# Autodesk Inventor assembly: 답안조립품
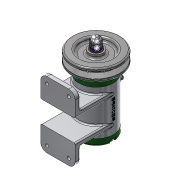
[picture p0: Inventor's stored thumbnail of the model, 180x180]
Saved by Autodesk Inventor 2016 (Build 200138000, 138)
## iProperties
Created: 2017-02
Part Number: 답안조립품
Material: 일반
Document SubType Name: Assembly
Designer: H
Author: H
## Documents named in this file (16)
- C:\Users\CAMTIC\Desktop\470207V1008\답안조립품.iam
- C:\Users\CAMTIC\Desktop\470207V1008\본체.ipt
- C:\Users\CAMTIC\Desktop\470207V1008\V벨트풀리.ipt
- C:\Users\CAMTIC\Desktop\470207V1008\너트 M 8.ipt
- C:\Users\CAMTIC\Desktop\470207V1008\니플 M 6 x 0.75.ipt
- C:\Users\CAMTIC\Desktop\470207V1008\뒤커버.ipt
- C:\Users\CAMTIC\Desktop\470207V1008\베어링 15 x 32 x 9.ipt
- C:\Users\CAMTIC\Desktop\470207V1008\볼트 M 6 x 8.ipt
- C:\Users\CAMTIC\Desktop\470207V1008\볼트 M4 x 12.ipt
- C:\Users\CAMTIC\Desktop\470207V1008\스프링와셔 8.ipt
- C:\Users\CAMTIC\Desktop\470207V1008\앞커버.ipt
- C:\Users\CAMTIC\Desktop\470207V1008\오일 실 15 25 7.ipt
- C:\Users\CAMTIC\Desktop\470207V1008\와셔 6x11.5.ipt
- C:\Users\CAMTIC\Desktop\470207V1008\와셔 8x17.ipt
- C:\Users\CAMTIC\Desktop\470207V1008\축.ipt
- C:\Users\CAMTIC\Desktop\470207V1008\키 3 x 3 x 12.ipt
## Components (11 placed, 3 different names)
1. V벨트풀리:1
2. KS B 2023 6002 - 15 x 32 x 9:1
3. KS B 2023 6002 - 15 x 32 x 9:2
4. ISO 4762 M4 x 12:1
5. ISO 4762 M4 x 12:3
6. ISO 4762 M4 x 12:4
7. ISO 4762 M4 x 12:5
8. ISO 4762 M4 x 12:2
9. ISO 4762 M4 x 12:6
10. ISO 4762 M4 x 12:7
11. ISO 4762 M4 x 12:8
